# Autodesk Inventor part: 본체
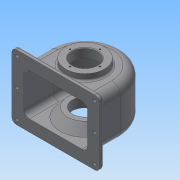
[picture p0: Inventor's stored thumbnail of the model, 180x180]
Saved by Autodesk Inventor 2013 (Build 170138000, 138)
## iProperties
Created: 2015-09
Part Number: 본체
Material: 일반
Document SubType Name: Modeling
Designer: Administrator
Density: 1 g/cm^3
Author: Administrator
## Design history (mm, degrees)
sketch "스케치1"
  geometry: L1 (-57, -47)-(57, -47); L2 (-57, 0)-(-57, -47); L3 (57, 0)-(57, -47); A1 r 57 centre (0, 0) between (57, 0) and (-57, 0); 2 further points
  constraints: 6 end point, 2 point on circle, 2 tangent, 1 centre point, 1 coincident, 1 horizontal, 1 midpoint, 1 parallel, 1 perpendicular, 1 vertical alignment
  dimensions: "d0" = 57 radius of A1; "d1" = 47 distance from line of A1.centre L1
extrude "돌출1" new body sketch "스케치1" distance "d2" = 77; taper "d3" = 0 deg
node "작업 평면1"
sketch "스케치3"
  geometry: L1 (-57, -47)-(-57, 0) reference; L2 (57, 0)-(57, -47) reference; L3 (57, -47)-(-57, -47) reference; L4 (-51, 0)-(-51, -47); L5 (51, 0)-(51, -47); A1 r 57 centre (0, 0) between (57, 0) and (-57, 0) reference; A2 r 51 centre (0, 0) between (51, 0) and (-51, 0); 1 further point
  constraints: 4 end point, 2 point on circle, 2 point on line, 2 tangent, 1 centre point, 1 coincident, 1 parallel, 1 perpendicular
  dimensions: "d20" = 51 radius of A2
extrude "돌출3" cut sketch "스케치3" stored distance "d21" = 67; taper "d22" = 0 deg
node "작업 평면2"
fillet "모깎기5" dims "d24" = 14
fillet "모깎기6" dims "d25" = 9
sketch "스케치4"
  geometry: C1 r 31 at (0, 0); 1 further point
  constraints: 1 centre point, 1 coincident
  dimensions: "d26" = 31 radius of C1
extrude "돌출4" join sketch "스케치4" stored distance "d27" = 67; taper "d28" = 0 deg
sketch "스케치8"
  geometry: L1 (43, 0)-(-47, 0) reference; L2 (-47, 0)-(-47, 5) reference; L3 (-47, 5)-(42, 5) reference; L4 (-31, 77)-(-31, 87) reference; L5 (-31, 87)-(31, 87) reference; L6 (42, 72)-(-47, 72) reference; L7 (-47, 72)-(-47, 77) reference; L8 (-47, 77)-(-31, 77) reference; L9 (57, 63)-(57, 14) reference; L10 (51, 14)-(51, 63) reference; L11 (31, 87)-(31, 77) reference; L12 (31, 77)-(43, 77) reference; L13 (0, 19)-(-28, 19); L14 (-28, 19)-(-43.943, 0); L15 (0, 19)-(0, 0); L16 (0, 0)-(-43.943, 0); A1 r 14 centre (43, 63) between (57, 63) and (43, 77) reference; A2 r 14 centre (43, 14) between (43, 0) and (57, 14) reference; A3 r 9 centre (42, 14) between (42, 5) and (51, 14) reference; A4 r 9 centre (42, 63) between (51, 63) and (42, 72) reference
  constraints: 8 end point, 2 perpendicular, 1 parallel, 1 point on line, 1 vertical alignment
  dimensions: "d50" = 28 distance of L13.start L13.end; "d51" = 68 distance between parallel lines of L13 L5; "d52" = 50 deg angle of L14 L13
revolve "회전3" sketch "스케치8" stored, may be unused: angle "d53" = 90 deg
sketch "스케치10"
  geometry: L1 (57, 63)-(57, 14) reference; L2 (43.918, 0.03)-(43.943, 0) reference; L3 (43.943, 0)-(-47, 0) reference; L4 (-47, 0)-(-47, 5) reference; L5 (-47, 5)-(-39.747, 5) reference; L6 (-39.747, 5)-(-28, 19) reference; L7 (-28, 19)-(28, 19) reference; L8 (28, 19)-(39.747, 5) reference; L9 (39.747, 5)-(42, 5) reference; L10 (51, 14)-(51, 63) reference; L11 (42, 72)-(-47, 72) reference; L12 (-47, 72)-(-47, 77) reference; L13 (-47, 77)-(-31, 77) reference; L14 (-31, 77)-(-31, 87) reference; L15 (-31, 87)-(31, 87) reference; L16 (31, 87)-(31, 77) reference; L17 (31, 77)-(43, 77) reference; L18 (37.416, 0)-(33, 5.263); L19 (0, 0)-(0, 3); L20 (0, 3)-(33, 3); L21 (33, 3)-(33, 5.263); A1 r 14 centre (43, 63) between (57, 63) and (43, 77) reference; A2 r 14 centre (43, 14) between (43.918, 0.03) and (57, 14) reference; A3 r 9 centre (42, 14) between (42, 5) and (51, 14) reference; A4 r 9 centre (42, 63) between (51, 63) and (42, 72) reference
  constraints: 8 end point, 3 perpendicular, 1 parallel, 1 point on line
  dimensions: "d63" = 5 distance between parallel lines of L18 L8; "d65" = 3 distance of L19.start L19.end; "d66" = 33 distance of L19.end L20.end
revolve "회전5" sketch "스케치10" stored, may be unused: angle "d67" = 90 deg
fillet "모깎기7" dims "d68" = 0.5
sketch "스케치11"
  geometry: C1 r 20 at (0, 0); 1 further point
  constraints: 1 centre point, 1 coincident
  dimensions: "d69" = 20 radius of C1
extrude "돌출6" cut sketch "스케치11" stored distance "d70" = 56; taper "d71" = 0 deg
sketch "스케치12"
  geometry: L1 (85, 72)-(1, 72) reference; L2 (-8, 63)-(-8, 14) reference; L3 (1, 5)-(85, 5) reference; L4 (94, 14)-(94, 63) reference; L5 (0, 77)-(86, 77) reference; L6 (100, 63)-(100, 14) reference; L7 (86, 0)-(0, 0) reference; L8 (-14, 14)-(-14, 63) reference; L9 (-27, 90.5)-(113, 90.5); L10 (113, 90.5)-(113, -13.5); L11 (113, -13.5)-(-27, -13.5); L12 (-27, -13.5)-(-27, 90.5); A1 r 9 centre (1, 63) between (1, 72) and (-8, 63) reference; A2 r 9 centre (1, 14) between (-8, 14) and (1, 5) reference; A3 r 9 centre (85, 14) between (85, 5) and (94, 14) reference; A4 r 9 centre (85, 63) between (94, 63) and (85, 72) reference; A5 r 14 centre (0, 63) between (0, 77) and (-14, 63) reference; A6 r 14 centre (86, 63) between (100, 63) and (86, 77) reference; A7 r 14 centre (86, 14) between (86, 0) and (100, 14) reference; A8 r 14 centre (0, 14) between (-14, 14) and (0, 0) reference; 1 further point
  constraints: 8 end point, 2 parallel, 1 horizontal, 1 perpendicular
  dimensions: "d72" = 140 distance of L10.end L11.end; "d73" = 104 distance of L9.end L10.end; "d74" = 13 distance between parallel lines of L8 L12; "d75" = 13.5 distance between parallel lines of L5 L9
extrude "돌출7" join sketch "스케치12" distance "d76" = 7; taper "d77" = 0 deg
fillet "모깎기8" dims "d78" = 7
fillet "모깎기9" dims "d79" = 1
fillet "모깎기10" dims "d80" = 3
sketch "스케치13"
  geometry: L1 (70, -43)-(70, -47) reference; L2 (70, -47)-(51, -47) reference; L3 (51, -47)-(51, 0) reference; L4 (-51, 0)-(-51, -47) reference; L5 (-51, -47)-(-70, -47) reference; L6 (-70, -47)-(-70, -43) reference; L7 (-67, -40)-(-58, -40) reference; L8 (-57, -39)-(-57, 0) reference; L9 (57, 0)-(57, -39) reference; L10 (58, -40)-(67, -40) reference; L11 (42, -47)-(-42, -47) reference; L12 (-6, 63)-(0, 63); L13 (0, 63)-(0, 54.506); L14 (-6, 63)-(-7.498, 54.506); L15 (-7.498, 54.506)-(0, 54.506); A1 r 3 centre (67, -43) between (70, -43) and (67, -40) reference; A2 r 51 centre (0, 0) between (51, 0) and (-51, 0) reference; A3 r 3 centre (-67, -43) between (-67, -40) and (-70, -43) reference; A4 r 1 centre (-58, -39) between (-58, -40) and (-57, -39) reference; A5 r 57 centre (0, 0) between (57, 0) and (-57, 0) reference; A6 r 1 centre (58, -39) between (57, -39) and (58, -40) reference; 2 further points
  constraints: 8 end point, 1 parallel, 1 perpendicular, 1 point on circle, 1 vertical alignment
  dimensions: "d83" = 6 distance of L12.start L12.end; "d84" = 6 distance from line of point (0, 57) L12; "d95" = 100 deg angle of L12 L14; "d96" = 8.49448 distance of L13.end L12.end; "d97" = 7.49781 distance of L14.end L13.end
revolve "회전6" sketch "스케치13" stored, may be unused: angle "d86" = 90 deg
sketch "스케치14"
  geometry: C1 r 6 at (0, 0) reference; 2 further points
  constraints: 1 coincident
hole "구멍1" sketch "스케치14" at (0, 0) diameter "d88" = 4.459; stored, may be unused: countersink angle "d92" = 90 deg, drill point angle "d94" = 118 deg; dims "d89" = 6, "d90" = 4, "d91" = 2, "d93" = 8
fillet "모깎기12" dims "d98" = 3
sketch "스케치15"
  geometry: L1 (69.062, -43)-(69.062, -47) reference; L2 (69.062, -47)-(-69.062, -47) reference; L3 (-69.062, -47)-(-69.062, -43) reference; L4 (-64.936, -40)-(64.936, -40) reference; C1 r 20 at (0, 0) reference; C2 r 31 at (0, 0) reference; 2 further points
  constraints: 1 vertical alignment, 2 other
  dimensions: "d99" = 24 distance of point (0, 0) point (0, 24)
hole "구멍2" sketch "스케치15" at (0, 24) diameter "d100" = 2.459; stored, may be unused: countersink angle "d104" = 90 deg, drill point angle "d106" = 118 deg; dims "d101" = 6, "d102" = 4, "d103" = 2, "d105" = 8
sketch "스케치16"
  geometry: L1 (-67, -40)-(-53.198, -40) reference; L2 (-51.66, -39)-(-51.66, 0) reference; L3 (51.66, 0)-(51.66, -39) reference; L4 (53.198, -40)-(67, -40) reference; L5 (70, -43)-(70, -47) reference; L6 (70, -47)-(-70, -47) reference; L7 (-70, -47)-(-70, -43) reference; C1 r 20 at (0, 0) reference; C2 r 34.899 at (0, 0) reference; C3 r 33 at (0, 0) reference; A1 r 3 centre (-67, -43) between (-67, -40) and (-70, -43) reference; A2 r 51.66 centre (0, 0) between (51.66, 0) and (-51.66, 0) reference; A3 r 3 centre (67, -43) between (70, -43) and (67, -40) reference; 2 further points
  constraints: 1 vertical alignment, 2 other
  dimensions: "d110" = 28 distance of point (0, 0) point (0, 28)
hole "구멍3" sketch "스케치16" at (0, 28) diameter "d111" = 2.459; stored, may be unused: countersink angle "d115" = 90 deg, drill point angle "d117" = 118 deg; dims "d112" = 7, "d113" = 4, "d114" = 2, "d116" = 9
chamfer "모따기1" distance "d121" = 1; stored, may be unused: second distance "d122" = 2, angle "d123" = 45 deg
fillet "모깎기13" dims "d124" = 3
sketch "스케치17"
  geometry: L1 (-14, -9.054)-(-14, -39) reference; L2 (-20.5, -47)-(69.5, -47) reference; 2 further points
  constraints: 1 other
  dimensions: "d125" = 38.5 distance from line of point (24.5, -17) L1; "d126" = 30 distance from line of point (24.5, -17) L2
feature "엠보싱1" sketch "스케치17" dims "d0" = 57, "d1" = 47, "d127" = 0.5, "d128" = 0
sketch "스케치18"
  geometry: L1 (-24, 6.5)-(-24, -83.5) reference; L2 (-20, -87.5)-(106, -87.5) reference; L3 (110, -83.5)-(110, 6.5) reference; L4 (106, 10.5)-(-20, 10.5) reference; L5 (86, -78)-(0, -78) reference; L6 (101, -14)-(101, -63) reference; L7 (0, 1)-(86, 1) reference; L8 (-15, -63)-(-15, -14) reference; L9 (1, -72)-(85, -72) reference; L10 (94, -63)-(94, -14) reference; L11 (85, -5)-(1, -5) reference; L12 (-8, -14)-(-8, -63) reference; L13 (106, 13.5)-(-20, 13.5) reference; L14 (-27, 6.5)-(-27, -83.5) reference; L15 (113, -83.5)-(113, 6.5) reference; C1 r 2.229 at (43, -38.5) reference; A1 r 4 centre (-20, -83.5) between (-24, -83.5) and (-20, -87.5) reference; A2 r 4 centre (106, -83.5) between (106, -87.5) and (110, -83.5) reference; A3 r 4 centre (106, 6.5) between (110, 6.5) and (106, 10.5) reference; A4 r 4 centre (-20, 6.5) between (-20, 10.5) and (-24, 6.5) reference; A5 r 15 centre (0, -63) between (-15, -63) and (0, -78) reference; A6 r 15 centre (86, -63) between (86, -78) and (101, -63) reference; A7 r 15 centre (86, -14) between (101, -14) and (86, 1) reference; A8 r 15 centre (0, -14) between (0, 1) and (-15, -14) reference; A9 r 9 centre (85, -63) between (85, -72) and (94, -63) reference; A10 r 9 centre (85, -14) between (94, -14) and (85, -5) reference; A11 r 9 centre (1, -14) between (1, -5) and (-8, -14) reference; A12 r 9 centre (1, -63) between (-8, -63) and (1, -72) reference; 7 further points
  constraints: 4 vertical alignment
  dimensions: "d132" = 8 distance from line of L13 point (-19, 5.5); "d133" = 44 distance of point (-19, 5.5) point (-19, -38.5); "d134" = 44 distance of point (-19, -38.5) point (-19, -82.5); "d135" = 8 distance from line of L13 point (105, 5.5); "d136" = 44 distance of point (105, 5.5) point (105, -38.5); "d137" = 44 distance of point (105, -38.5) point (105, -82.5); "d138" = 8 distance from line of L14 point (-19, -82.5); "d139" = 8 distance from line of L15 point (105, -82.5)
hole "구멍4" sketch "스케치18" at (-19, 5.5), (-19, -38.5), (-19, -82.5), (105, -82.5), (105, -38.5), (105, 5.5) diameter "d140" = 5; stored, may be unused: countersink angle "d144" = 90 deg, drill point angle "d146" = 118 deg; dims "d141" = 6, "d142" = 4, "d143" = 2, "d145" = 8
node "솔리드1"
pattern_circular "원형 패턴1" dims angle "d108" = 360 deg
pattern_circular "원형 패턴2" dims angle "d119" = 360 deg
node "절단 모서리 투영2"
node "절단 모서리 투영5"
node "절단 모서리 투영7"
node "절단 모서리 투영8"
node "절단 모서리 투영9"
node "절단 모서리 투영10"
node "절단 모서리 투영11"
node "절단 모서리 투영12"
node "절단 모서리 투영13"
other parameters: "d13" = 38.5, "d23" = 87
